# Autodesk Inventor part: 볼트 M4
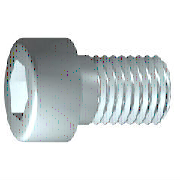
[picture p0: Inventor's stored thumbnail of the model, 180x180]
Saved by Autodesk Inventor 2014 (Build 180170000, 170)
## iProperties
IsCustomPart: 1
Created: 2015-10
Part Number: 볼트 M4
Material: 스테인리스강
Description: 6각머리 태핑 나사
Document SubType Name: Modeling
Standard: KS B 1003
Designer: mdu
Standards Organization: KS
Language: ko-KR
Size Designation: M 4 x 16
Categories: <MemberInstance><Categories><Category DisplayName="조임쇠" InternalName="e4da775c-781d-43d5-af7c-5136215cf5a6" Mnemonic="FSTN"><Category DisplayName="볼트" InternalN
Density: 8.08 g/cm^3
Mass: 2.70334 g
Surface Area: 3.81118 cm^2
Volume: 0.334572 cm^3
Appearance: 반광택
Author: mdu
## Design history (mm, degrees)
sketch "스케치1"
  geometry: L1 (-1, 0)-(16, 0); L2 (16, 0)-(16, 2); L3 (16, 2)-(1.75, 2); L4 (1.75, 2)-(1.32, 2); L5 (1.32, 2)-(0, 2); L6 (0, 2)-(0, 3.5); L7 (0, 3.5)-(-4, 3.5); L8 (-4, 3.5)-(-4, 1.732); L9 (-4, 1.732)-(-2, 1.732); L10 (-2, 1.732)-(-1, 0); L11 (-8, 0)-(20, 0) reference; L12 (0, -0.7)-(0, 4.2) reference; L13 (1.75, 2)-(0, 2)
  constraints: 22 end point, 6 parallel, 2 collinear, 2 perpendicular, 1 horizontal, 1 point on line
  dimensions: "d1" = 14.25 distance from line of L3.end L2 (= GEL); "d2" = 0.42952 distance of L4.end L3.end (computed from GAL); "d3" = 4 distance between parallel lines of L8 L6 (= KOH); "d4" = 2 distance of L8.end L9.end (= INTI); "d5" = 60 deg angle of L10 L1; "d6" = 4 diameter of L3 L1 (= GD); "d7" = 4 diameter of L5 L1 (= BDM); "d8" = 3.4641 diameter of L9 L1 (= 1.1547 x SW); "d9" = 7 diameter of L7 L1 (= KOD); "d26" = 16 distance between parallel lines of L12 L2 (= NLG)
revolve "본체" sketch "스케치1" stored, may be unused: angle "d10" = 90 deg
sketch "스케치2"
  geometry: L1 (0, -4.9)-(0, 4.9) reference; L2 (-4.9, 0)-(4.9, 0) reference; L3 (1.732, 0)-(0.866, -1.5); L4 (0.866, -1.5)-(-0.866, -1.5); L5 (-0.866, -1.5)-(-1.732, 0); L6 (-1.732, 0)-(-0.866, 1.5); L7 (-0.866, 1.5)-(0.866, 1.5); L8 (0.866, 1.5)-(1.732, 0); 2 further points
  constraints: 12 end point, 1 coincident, 1 horizontal alignment, 1 point on line, 12 other
extrude "슬롯" join sketch "스케치2" stored distance "d11" = 10; taper "d12" = 0 deg
workplane "Work Plane1"
fillet "Fillet2" dims "d30" = 0.1 (= R)
body "Solid1"
fillet "모깎기1" dims "d17" = 0.4 (= RR)
feature "스레드" dims "d13" = 14.25 (= GEL), "d14" = 0
chamfer "모따기1" distance "d15" = 0.42941 (= -0.5 x SPD + 0.5 x GD); stored, may be unused: second distance "d16" = 0.42941 (= GUL), angle "d27" = 45 deg
other parameters: "GD" = 4 (= NND) [user parameter; used in 2 equation terms], "NLG" = 16 [user parameter; used in 1 equation term], "GEL" = 14.25 [user parameter; used in 2 equation terms], "KOD" = 7 [user parameter; used in 1 equation term], "KOH" = 4 [user parameter; used in 1 equation term], "INTI" = 2 [user parameter; used in 1 equation term], "GAL" = 0.42941 (= 0.61345 x PTC) [user parameter; used in 1 equation term], "GUL" = 0.42941 (= 0.61345 x PTC) [user parameter; used in 1 equation term], "BDM" = 4 (= NND) [user parameter; used in 1 equation term], "SW" = 3 [user parameter; used in 2 equation terms], "RR" = 0.4 [user parameter; used in 1 equation term], "SPD" = 3.14117 (= NND - 1.2269 x PTC) [user parameter; used in 1 equation term], "d19" = 0, "d28" = 0, "d29" = 0, "R" = 0.1 [user parameter; used in 1 equation term], "PHH" = 0.2 [user parameter], "GD1" = 3.14117 (= THREADDIA - 1.2269 x PTC) [user parameter], "THREADDIA" = 4 [user parameter; used in 1 equation term], "FAWI" = 45 deg [user parameter], "TPU" = 14.28571 (computed from PTC) [user parameter], "PTC" = 0.7 [user parameter; used in 5 equation terms], "NND" = 4 [user parameter; used in 3 equation terms], "TOA" = 30 deg [user parameter], "E0" = 3.465 (= 1.155 x SW) [user parameter]
